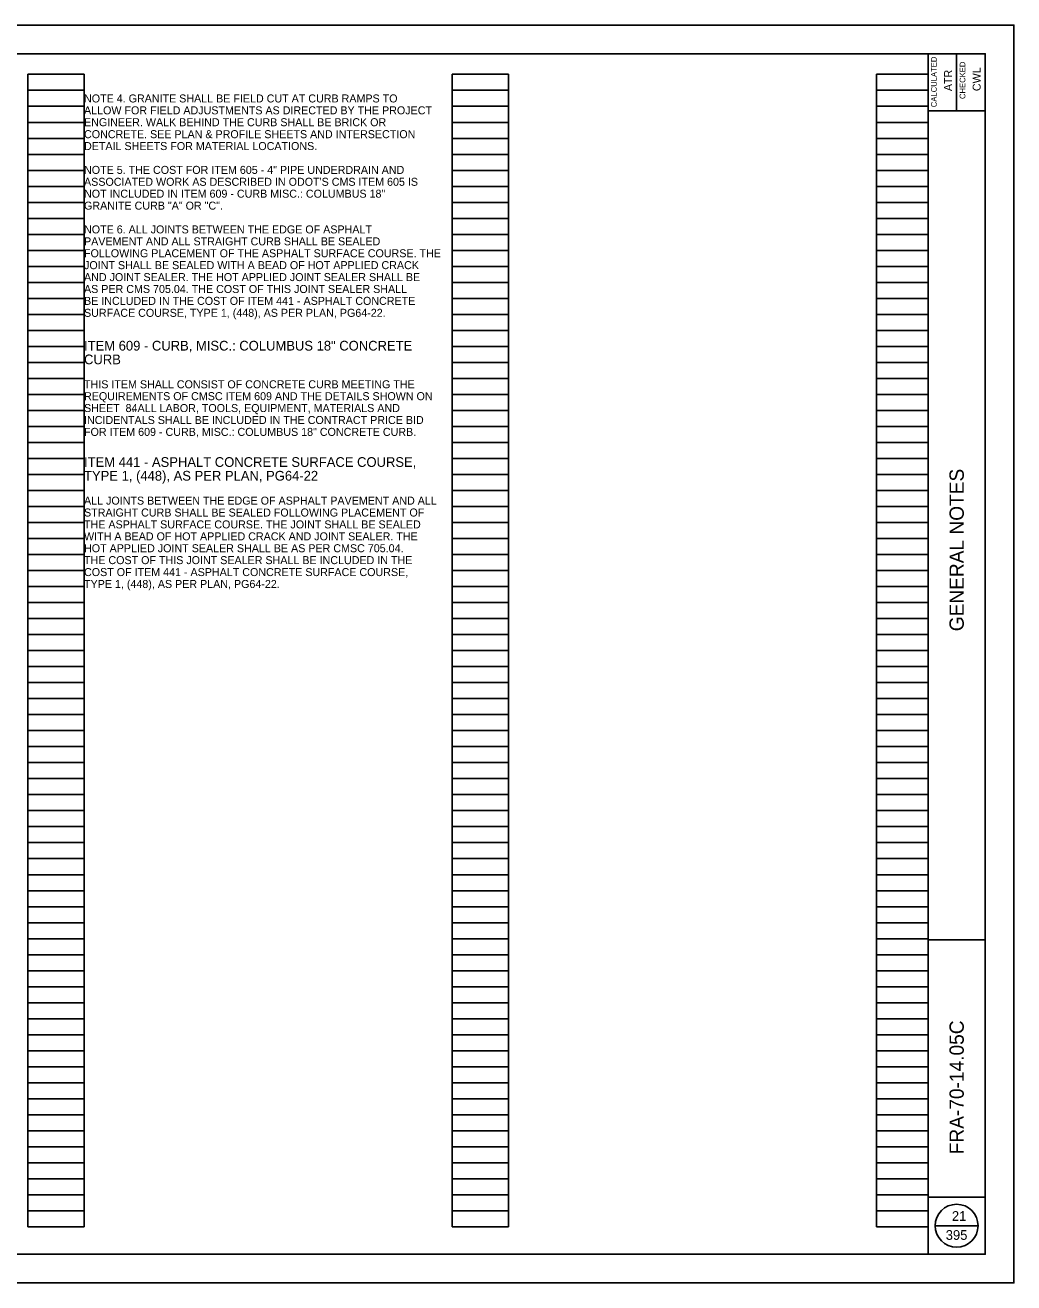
# Model space of a CAD drawing. Extents: x 0 to 34, y 0 to 22.
# Drawn here: x 16.71 to 34, y 0 to 22 of the extents above; entities that cross this region are included whole.
import ezdxf

# ---------------------------------------------------------------- set-up
doc = ezdxf.new("R2010")
doc.units = 0
for name, color, linetype in [('SC_Scratch1', 7, 'Continuous'), ('SH_Border', 7, 'Continuous'), ('SH_Cut_Line', 7, 'Continuous'), ('SH_Data', 7, 'Continuous'), ('TX_P_1', 7, 'Continuous')]:
    doc.layers.add(name, color=color, linetype=linetype)

msp = doc.modelspace()

# ---------------------------------------------------------------- linework, layer by layer
at = {"layer": 'SC_Scratch1'}
for p, q in [((16.76, 0.98), (16.76, 21.14)), ((16.76, 21.14), (17.74, 21.14)), ((17.74, 0.98), (17.74, 21.14)), ((24.18, 0.98), (24.18, 21.14)), ((24.18, 21.14), (25.16, 21.14)), ((25.16, 0.98), (25.16, 21.14)), ((31.6, 0.98), (31.6, 21.14)), ((31.6, 21.14), (32.5, 21.14)), ((32.5, 0.98), (32.5, 21.14)), ((16.76, 20.86), (17.74, 20.86)), ((24.18, 20.86), (25.16, 20.86)), ((31.6, 20.86), (32.5, 20.86)), ((16.76, 20.58), (17.74, 20.58)), ((24.18, 20.58), (25.16, 20.58)), ((31.6, 20.58), (32.5, 20.58)), ((16.76, 20.3), (17.74, 20.3)), ((24.18, 20.3), (25.16, 20.3)), ((31.6, 20.3), (32.5, 20.3)), ((16.76, 20.02), (17.74, 20.02)), ((24.18, 20.02), (25.16, 20.02)), ((31.6, 20.02), (32.5, 20.02)), ((16.76, 19.74), (17.74, 19.74)), ((24.18, 19.74), (25.16, 19.74)), ((31.6, 19.74), (32.5, 19.74)), ((16.76, 19.46), (17.74, 19.46)), ((24.18, 19.46), (25.16, 19.46)), ((31.6, 19.46), (32.5, 19.46)), ((16.76, 19.18), (17.74, 19.18)), ((24.18, 19.18), (25.16, 19.18)), ((31.6, 19.18), (32.5, 19.18)), ((16.76, 18.9), (17.74, 18.9)), ((24.18, 18.9), (25.16, 18.9)), ((31.6, 18.9), (32.5, 18.9)), ((16.76, 18.62), (17.74, 18.62)), ((24.18, 18.62), (25.16, 18.62)), ((31.6, 18.62), (32.5, 18.62)), ((16.76, 18.34), (17.74, 18.34)), ((24.18, 18.34), (25.16, 18.34)), ((31.6, 18.34), (32.5, 18.34)), ((16.76, 18.06), (17.74, 18.06)), ((24.18, 18.06), (25.16, 18.06)), ((31.6, 18.06), (32.5, 18.06)), ((16.76, 17.78), (17.74, 17.78)), ((24.18, 17.78), (25.16, 17.78)), ((31.6, 17.78), (32.5, 17.78)), ((16.76, 17.5), (17.74, 17.5)), ((24.18, 17.5), (25.16, 17.5)), ((31.6, 17.5), (32.5, 17.5)), ((16.76, 17.22), (17.74, 17.22)), ((24.18, 17.22), (25.16, 17.22)), ((31.6, 17.22), (32.5, 17.22)), ((16.76, 16.94), (17.74, 16.94)), ((24.18, 16.94), (25.16, 16.94)), ((31.6, 16.94), (32.5, 16.94)), ((16.76, 16.66), (17.74, 16.66)), ((24.18, 16.66), (25.16, 16.66)), ((31.6, 16.66), (32.5, 16.66)), ((16.76, 16.38), (17.74, 16.38)), ((24.18, 16.38), (25.16, 16.38)), ((31.6, 16.38), (32.5, 16.38)), ((16.76, 16.1), (17.74, 16.1)), ((24.18, 16.1), (25.16, 16.1)), ((31.6, 16.1), (32.5, 16.1)), ((16.76, 15.82), (17.74, 15.82)), ((24.18, 15.82), (25.16, 15.82)), ((31.6, 15.82), (32.5, 15.82)), ((16.76, 15.54), (17.74, 15.54)), ((24.18, 15.54), (25.16, 15.54)), ((31.6, 15.54), (32.5, 15.54)), ((16.76, 15.26), (17.74, 15.26)), ((24.18, 15.26), (25.16, 15.26)), ((31.6, 15.26), (32.5, 15.26)), ((16.76, 14.98), (17.74, 14.98)), ((24.18, 14.98), (25.16, 14.98)), ((31.6, 14.98), (32.5, 14.98)), ((16.76, 14.7), (17.74, 14.7)), ((24.18, 14.7), (25.16, 14.7)), ((31.6, 14.7), (32.5, 14.7)), ((16.76, 14.42), (17.74, 14.42)), ((24.18, 14.42), (25.16, 14.42)), ((31.6, 14.42), (32.5, 14.42)), ((16.76, 14.14), (17.74, 14.14)), ((24.18, 14.14), (25.16, 14.14)), ((31.6, 14.14), (32.5, 14.14)), ((16.76, 13.86), (17.74, 13.86)), ((24.18, 13.86), (25.16, 13.86)), ((31.6, 13.86), (32.5, 13.86)), ((16.76, 13.58), (17.74, 13.58)), ((24.18, 13.58), (25.16, 13.58)), ((31.6, 13.58), (32.5, 13.58)), ((16.76, 13.3), (17.74, 13.3)), ((24.18, 13.3), (25.16, 13.3)), ((31.6, 13.3), (32.5, 13.3)), ((16.76, 13.02), (17.74, 13.02)), ((24.18, 13.02), (25.16, 13.02)), ((31.6, 13.02), (32.5, 13.02)), ((16.76, 12.74), (17.74, 12.74)), ((24.18, 12.74), (25.16, 12.74)), ((31.6, 12.74), (32.5, 12.74)), ((16.76, 12.46), (17.74, 12.46)), ((24.18, 12.46), (25.16, 12.46)), ((31.6, 12.46), (32.5, 12.46)), ((16.76, 12.18), (17.74, 12.18)), ((24.18, 12.18), (25.16, 12.18)), ((31.6, 12.18), (32.5, 12.18)), ((16.76, 11.9), (17.74, 11.9)), ((24.18, 11.9), (25.16, 11.9)), ((31.6, 11.9), (32.5, 11.9)), ((16.76, 11.62), (17.74, 11.62)), ((24.18, 11.62), (25.16, 11.62)), ((31.6, 11.62), (32.5, 11.62)), ((16.76, 11.34), (17.74, 11.34)), ((24.18, 11.34), (25.16, 11.34)), ((31.6, 11.34), (32.5, 11.34)), ((16.76, 11.06), (17.74, 11.06)), ((24.18, 11.06), (25.16, 11.06)), ((31.6, 11.06), (32.5, 11.06)), ((16.76, 10.78), (17.74, 10.78)), ((24.18, 10.78), (25.16, 10.78)), ((31.6, 10.78), (32.5, 10.78)), ((16.76, 10.5), (17.74, 10.5)), ((24.18, 10.5), (25.16, 10.5)), ((31.6, 10.5), (32.5, 10.5)), ((16.76, 10.22), (17.74, 10.22)), ((24.18, 10.22), (25.16, 10.22)), ((31.6, 10.22), (32.5, 10.22)), ((16.76, 9.94), (17.74, 9.94)), ((24.18, 9.94), (25.16, 9.94)), ((31.6, 9.94), (32.5, 9.94)), ((16.76, 9.66), (17.74, 9.66)), ((24.18, 9.66), (25.16, 9.66)), ((31.6, 9.66), (32.5, 9.66)), ((16.76, 9.38), (17.74, 9.38)), ((24.18, 9.38), (25.16, 9.38)), ((31.6, 9.38), (32.5, 9.38)), ((16.76, 9.1), (17.74, 9.1)), ((24.18, 9.1), (25.16, 9.1)), ((31.6, 9.1), (32.5, 9.1)), ((16.76, 8.82), (17.74, 8.82)), ((24.18, 8.82), (25.16, 8.82)), ((31.6, 8.82), (32.5, 8.82)), ((16.76, 8.54), (17.74, 8.54)), ((24.18, 8.54), (25.16, 8.54)), ((31.6, 8.54), (32.5, 8.54)), ((16.76, 8.26), (17.74, 8.26)), ((24.18, 8.26), (25.16, 8.26)), ((31.6, 8.26), (32.5, 8.26)), ((16.76, 7.98), (17.74, 7.98)), ((24.18, 7.98), (25.16, 7.98)), ((31.6, 7.98), (32.5, 7.98)), ((16.76, 7.7), (17.74, 7.7)), ((24.18, 7.7), (25.16, 7.7)), ((31.6, 7.7), (32.5, 7.7)), ((16.76, 7.42), (17.74, 7.42)), ((24.18, 7.42), (25.16, 7.42)), ((31.6, 7.42), (32.5, 7.42)), ((16.76, 7.14), (17.74, 7.14)), ((24.18, 7.14), (25.16, 7.14)), ((31.6, 7.14), (32.5, 7.14)), ((16.76, 6.86), (17.74, 6.86)), ((24.18, 6.86), (25.16, 6.86)), ((31.6, 6.86), (32.5, 6.86)), ((16.76, 6.58), (17.74, 6.58)), ((24.18, 6.58), (25.16, 6.58)), ((31.6, 6.58), (32.5, 6.58)), ((16.76, 6.3), (17.74, 6.3)), ((24.18, 6.3), (25.16, 6.3)), ((31.6, 6.3), (32.5, 6.3)), ((16.76, 6.02), (17.74, 6.02)), ((24.18, 6.02), (25.16, 6.02)), ((31.6, 6.02), (32.5, 6.02)), ((16.76, 5.74), (17.74, 5.74)), ((24.18, 5.74), (25.16, 5.74)), ((31.6, 5.74), (32.5, 5.74)), ((16.76, 5.46), (17.74, 5.46)), ((24.18, 5.46), (25.16, 5.46)), ((31.6, 5.46), (32.5, 5.46)), ((16.76, 5.18), (17.74, 5.18)), ((24.18, 5.18), (25.16, 5.18)), ((31.6, 5.18), (32.5, 5.18)), ((16.76, 4.9), (17.74, 4.9)), ((24.18, 4.9), (25.16, 4.9)), ((31.6, 4.9), (32.5, 4.9)), ((16.76, 4.62), (17.74, 4.62)), ((24.18, 4.62), (25.16, 4.62)), ((31.6, 4.62), (32.5, 4.62)), ((16.76, 4.34), (17.74, 4.34)), ((24.18, 4.34), (25.16, 4.34)), ((31.6, 4.34), (32.5, 4.34)), ((16.76, 4.06), (17.74, 4.06)), ((24.18, 4.06), (25.16, 4.06)), ((31.6, 4.06), (32.5, 4.06)), ((16.76, 3.78), (17.74, 3.78)), ((24.18, 3.78), (25.16, 3.78)), ((31.6, 3.78), (32.5, 3.78)), ((16.76, 3.5), (17.74, 3.5)), ((24.18, 3.5), (25.16, 3.5)), ((31.6, 3.5), (32.5, 3.5)), ((16.76, 3.22), (17.74, 3.22)), ((24.18, 3.22), (25.16, 3.22)), ((31.6, 3.22), (32.5, 3.22)), ((16.76, 2.94), (17.74, 2.94)), ((24.18, 2.94), (25.16, 2.94)), ((31.6, 2.94), (32.5, 2.94)), ((16.76, 2.66), (17.74, 2.66)), ((24.18, 2.66), (25.16, 2.66)), ((31.6, 2.66), (32.5, 2.66)), ((16.76, 2.38), (17.74, 2.38)), ((24.18, 2.38), (25.16, 2.38)), ((31.6, 2.38), (32.5, 2.38)), ((16.76, 2.1), (17.74, 2.1)), ((24.18, 2.1), (25.16, 2.1)), ((31.6, 2.1), (32.5, 2.1)), ((16.76, 1.82), (17.74, 1.82)), ((24.18, 1.82), (25.16, 1.82)), ((31.6, 1.82), (32.5, 1.82)), ((16.76, 1.54), (17.74, 1.54)), ((24.18, 1.54), (25.16, 1.54)), ((31.6, 1.54), (32.5, 1.54)), ((16.76, 1.26), (17.74, 1.26)), ((24.18, 1.26), (25.16, 1.26)), ((31.6, 1.26), (32.5, 1.26)), ((16.76, 0.98), (17.74, 0.98)), ((24.18, 0.98), (25.16, 0.98)), ((31.6, 0.98), (32.5, 0.98))]:
    msp.add_line(p, q, dxfattribs=at)
at = {"layer": 'SH_Border'}
for p, q in [((32.5, 0.5), (32.5, 21.5)), ((33, 21.5), (33, 20.5)), ((32.5, 20.5), (33.5, 20.5)), ((32.5, 6), (33.5, 6)), ((32.5, 1.5), (33.5, 1.5))]:
    msp.add_line(p, q, dxfattribs=at)
msp.add_lwpolyline([(2, 21.5), (33.5, 21.5), (33.5, 0.5), (2, 0.5)], close=True, dxfattribs=at)
at = {"layer": 'SH_Cut_Line'}
msp.add_lwpolyline([(0, 0), (34, 0), (34, 22), (0, 22)], close=True, dxfattribs=at)
at = {"layer": 'SH_Data'}
msp.add_line((32.625, 1), (33.375, 1), dxfattribs=at)
msp.add_circle((33, 1), 0.375, dxfattribs=at)

# ---------------------------------------------------------------- texts
for s, height, p in [('CALCULATED', 0.1, (32.652, 20.565)), ('CHECKED', 0.1, (33.152, 20.708)), ('ATR', 0.14, (32.92, 20.846)), ('CWL', 0.14, (33.42, 20.846)), ('GENERAL NOTES', 0.25, (33.125, 11.398)), ('FRA-70-14.05C', 0.25, (33.125, 2.249))]:
    msp.add_text(s, height=height, rotation=90, dxfattribs=at).set_placement(p)
for s, height, p in [('84', 0.14, (18.466, 15.232)), ('21', 0.17, (32.917, 1.084)), ('395', 0.17, (32.809, 0.752))]:
    msp.add_text(s, height=height, dxfattribs=at).set_placement(p)
at = {"layer": 'TX_P_1'}
for s, height, p in [('NOTE 4. GRANITE SHALL BE FIELD CUT AT CURB RAMPS TO ', 0.14, (17.74, 20.648)), ('ALLOW FOR FIELD ADJUSTMENTS AS DIRECTED BY THE PROJECT ', 0.14, (17.74, 20.44)), ('ENGINEER. WALK BEHIND THE CURB SHALL BE BRICK OR ', 0.14, (17.74, 20.232)), ('CONCRETE. SEE PLAN & PROFILE SHEETS AND INTERSECTION ', 0.14, (17.74, 20.023)), ('DETAIL SHEETS FOR MATERIAL LOCATIONS.', 0.14, (17.74, 19.815)), ('NOTE 5. THE COST FOR ITEM 605 - 4" PIPE UNDERDRAIN AND ', 0.14, (17.74, 19.398)), ("ASSOCIATED WORK AS DESCRIBED IN ODOT'S CMS ITEM 605 IS ", 0.14, (17.74, 19.19)), ('NOT INCLUDED IN ITEM 609 - CURB MISC.: COLUMBUS 18" ', 0.14, (17.74, 18.982)), ('GRANITE CURB "A" OR "C".', 0.14, (17.74, 18.773)), ('NOTE 6. ALL JOINTS BETWEEN THE EDGE OF ASPHALT ', 0.14, (17.74, 18.357)), ('PAVEMENT AND ALL STRAIGHT CURB SHALL BE SEALED ', 0.14, (17.74, 18.148)), ('FOLLOWING PLACEMENT OF THE ASPHALT SURFACE COURSE. THE ', 0.14, (17.74, 17.94)), ('JOINT SHALL BE SEALED WITH A BEAD OF HOT APPLIED CRACK ', 0.14, (17.74, 17.732)), ('AND JOINT SEALER. THE HOT APPLIED JOINT SEALER SHALL BE ', 0.14, (17.74, 17.523)), ('AS PER CMS 705.04. THE COST OF THIS JOINT SEALER SHALL ', 0.14, (17.74, 17.315)), ('BE INCLUDED IN THE COST OF ITEM 441 - ASPHALT CONCRETE ', 0.14, (17.74, 17.107)), ('SURFACE COURSE, TYPE 1, (448), AS PER PLAN, PG64-22.', 0.14, (17.74, 16.898)), ('ITEM 609 - CURB, MISC.: COLUMBUS 18" CONCRETE ', 0.17, (17.74, 16.308)), ('CURB', 0.17, (17.74, 16.068)), ('THIS ITEM SHALL CONSIST OF CONCRETE CURB MEETING THE ', 0.14, (17.74, 15.648)), ('REQUIREMENTS OF CMSC ITEM 609 AND THE DETAILS SHOWN ON ', 0.14, (17.74, 15.44)), ('SHEET    . ALL LABOR, TOOLS, EQUIPMENT, MATERIALS AND ', 0.14, (17.74, 15.232)), ('INCIDENTALS SHALL BE INCLUDED IN THE CONTRACT PRICE BID ', 0.14, (17.74, 15.023)), ('FOR ITEM 609 - CURB, MISC.: COLUMBUS 18" CONCRETE CURB.', 0.14, (17.74, 14.815)), ('ITEM 441 - ASPHALT CONCRETE SURFACE COURSE, ', 0.17, (17.74, 14.273)), ('TYPE 1, (448), AS PER PLAN, PG64-22', 0.17, (17.74, 14.033)), ('ALL JOINTS BETWEEN THE EDGE OF ASPHALT PAVEMENT AND ALL ', 0.14, (17.74, 13.613)), ('STRAIGHT CURB SHALL BE SEALED FOLLOWING PLACEMENT OF ', 0.14, (17.74, 13.405)), ('THE ASPHALT SURFACE COURSE. THE JOINT SHALL BE SEALED ', 0.14, (17.74, 13.197)), ('WITH A BEAD OF HOT APPLIED CRACK AND JOINT SEALER. THE ', 0.14, (17.74, 12.988)), ('HOT APPLIED JOINT SEALER SHALL BE AS PER CMSC 705.04. ', 0.14, (17.74, 12.78)), ('THE COST OF THIS JOINT SEALER SHALL BE INCLUDED IN THE ', 0.14, (17.74, 12.572)), ('COST OF ITEM 441 - ASPHALT CONCRETE SURFACE COURSE, ', 0.14, (17.74, 12.363)), ('TYPE 1, (448), AS PER PLAN, PG64-22.', 0.14, (17.74, 12.155))]:
    msp.add_text(s, height=height, dxfattribs=at).set_placement(p)

doc.saveas('drawing.dxf')
